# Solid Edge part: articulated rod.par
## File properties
Author: Robert a Rhodes jr
Template: Normal.par
Last saved by: CADCIM
Revision: 11
Application: Solid Edge
Accuracy: 0.99
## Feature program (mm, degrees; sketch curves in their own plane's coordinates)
pattern "unnamed Pattern 1"
pattern "unnamed Pattern 2"
Other named dimensions: "Hole_2": Diameter = 15 mm
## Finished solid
Body 1: solid body, 26 faces, 56 edges, 32 vertices.
  Faces by surface: plane 14, cylinder 12
  Edges by curve: circle 28, line 28
Bounding box of the edges (mm): 207.500 x 35.000 x 42.000, from (-101, -17.5, -21) to (106.5, 17.5, 21).
Cylindrical faces by radius (mm): R6.35 x4, R7.5 x1, R12 x2, R17.5 x1, R24 x4
Planar faces by outward normal: +y 3, +z 4, -y 3, -z 4
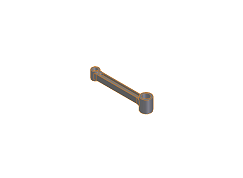
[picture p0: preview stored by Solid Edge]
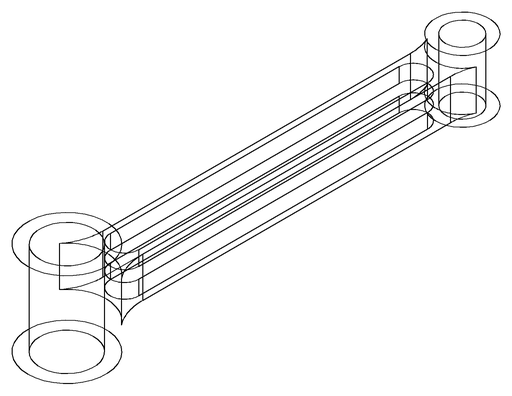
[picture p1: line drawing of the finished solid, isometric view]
